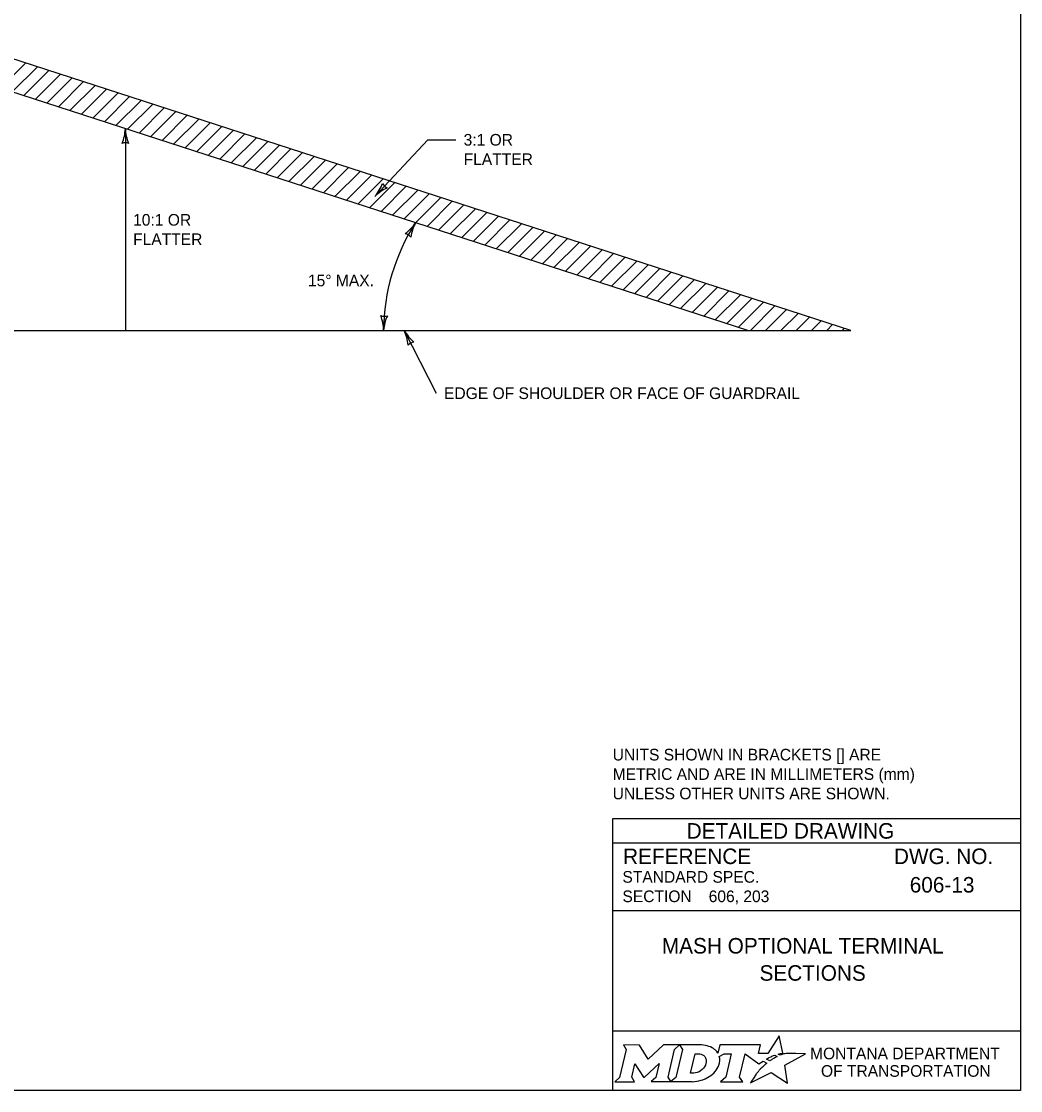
# Model space of a CAD drawing. Extents: x 49991.4 to 50021, y 49987.6 to 50011.4.
# Drawn here: x 50011.61 to 50016.75, y 49987.8 to 49993.3 of the extents above; entities that cross this region are included whole.
import ezdxf

# ---------------------------------------------------------------- set-up
doc = ezdxf.new("R2010")
doc.units = 0
for name, color, linetype in [('Default', 7, 'Continuous'), ('Level 1', 7, 'Continuous'), ('Level 2', 7, 'Continuous'), ('Level 3', 7, 'Continuous'), ('Level 5', 7, 'Continuous')]:
    doc.layers.add(name, color=color, linetype=linetype)

msp = doc.modelspace()

# ---------------------------------------------------------------- linework, layer by layer
at = {"layer": 'Default'}
for points in [[(50015.5126, 49987.9811), (50015.5023, 49987.9867), (50015.5139, 49987.9895), (50015.5255, 49987.9915), (50015.5081, 49988.0816), (50015.4486, 49987.9903), (50015.4013, 49987.9896), (50015.4116, 49988.0337), (50015.2024, 49988.0338), (50015.1923, 49987.9913), (50015.1865, 49987.9996)], [(50014.7056, 49988.0338), (50014.7197, 49988.0104), (50014.6862, 49987.8671), (50014.6605, 49987.8446), (50014.7621, 49987.8446), (50014.7486, 49987.8674), (50014.7648, 49987.9375), (50014.8085, 49987.8685), (50014.8138, 49987.8685), (50014.8889, 49987.938), (50014.8725, 49987.8669), (50014.8478, 49987.8449), (50014.9494, 49987.8449), (50014.9356, 49987.8682), (50014.9688, 49988.0106)], [(50014.9688, 49988.0106), (50014.9941, 49988.0338), (50014.9117, 49988.0338), (50014.8321, 49987.9608), (50014.7876, 49988.0335), (50014.7056, 49988.0338)], [(50015.1077, 49988.0338), (50014.9941, 49988.0338), (50015.0088, 49988.0109), (50014.9749, 49987.8671), (50014.9494, 49987.8449), (50015.06, 49987.8449)], [(50015.1317, 49987.9471), (50015.1305, 49987.939), (50015.1273, 49987.9297), (50015.1231, 49987.9215), (50015.1175, 49987.914), (50015.111, 49987.9071), (50015.1031, 49987.9008), (50015.0948, 49987.8961), (50015.0857, 49987.8922), (50015.0766, 49987.8899), (50015.0674, 49987.889), (50015.0515, 49987.889), (50015.0751, 49987.989), (50015.0911, 49987.989), (50015.0987, 49987.9884), (50015.1063, 49987.9865), (50015.1129, 49987.9835), (50015.119, 49987.9793), (50015.1238, 49987.9743), (50015.1275, 49987.9683), (50015.1302, 49987.9621), (50015.1318, 49987.9547), (50015.1318, 49987.9517), (50015.1317, 49987.9471)], [(50015.1991, 49987.9747), (50015.2237, 49987.9878), (50015.2606, 49987.9878), (50015.232, 49987.8673), (50015.2045, 49987.8446), (50015.3207, 49987.8446), (50015.3037, 49987.8675), (50015.3319, 49987.9877), (50015.4032, 49987.936), (50015.4243, 49987.9511), (50015.444, 49987.9402)], [(50015.3882, 49987.8843), (50015.3729, 49987.8599), (50015.3682, 49987.8524), (50015.3624, 49987.8438), (50015.3601, 49987.8395), (50015.4654, 49987.8926), (50015.5493, 49987.8375), (50015.5362, 49987.9302), (50015.6431, 49987.9886), (50015.5938, 49987.9894), (50015.5637, 49987.9898), (50015.5429, 49987.9901), (50015.5361, 49987.9886), (50015.5312, 49987.9874), (50015.5228, 49987.9851), (50015.5126, 49987.9811)], [(50015.4622, 49987.9535), (50015.4598, 49987.9518), (50015.4415, 49987.9614), (50015.4518, 49987.9671), (50015.4559, 49987.9693), (50015.4645, 49987.9733), (50015.4702, 49987.9759), (50015.4781, 49987.9789), (50015.4854, 49987.9816), (50015.4972, 49987.9742), (50015.4932, 49987.9721), (50015.4886, 49987.9696), (50015.4844, 49987.9674), (50015.4794, 49987.9645), (50015.4775, 49987.9634), (50015.4748, 49987.9618), (50015.4723, 49987.9604), (50015.47, 49987.9588), (50015.4674, 49987.957), (50015.4647, 49987.9552), (50015.4622, 49987.9535)], [(50015.4021, 49987.9004), (50015.4021, 49987.9004)], [(50015.1057, 49987.8522), (50015.1141, 49987.8548), (50015.1271, 49987.8602), (50015.1475, 49987.8712)]]:
    msp.add_lwpolyline(points, dxfattribs=at)
for centre, radius, start, end in [((50015.1308, 49987.9554), 0.0709, 339.5329, 15.8582), ((50015.0868, 49987.9727), 0.1183, 300.9103, 339.1383)]:
    msp.add_arc(centre, radius, start, end, dxfattribs=at)
for centre, major_axis, ratio, start_param, end_param in [((50015.1056, 49987.9864), (0.0834, -0.0037), 0.568097, 0.61298, 1.570796), ((50015.1612, 49987.9937), (0.0361, -0.0295), 0.469099, 1.225588, 1.570796), ((50015.3952, 49987.8923), (-0.00694, -0.00806), 0.008222, 0, 3.137361), ((50015.4119, 49987.9106), (-0.0098, -0.0102), 0.016458, 3.141593, 6.279097), ((50015.4329, 49987.9305), (-0.0112, -0.0097), 0.021651, 3.157348, 6.283185), ((50015.0603, 49987.9932), (0, 0.1484), 0.987302, 3.139398, 3.456847)]:
    msp.add_ellipse(centre, major_axis=major_axis, ratio=ratio, start_param=start_param, end_param=end_param, dxfattribs=at)
at = {"layer": 'Level 1'}
for p, q in [((50015.8765, 49991.7129), (50011.0311, 49993.2847)), ((50015.3468, 49991.713), (50011.0311, 49993.1129)), ((50011.6297, 49993.0905), (50011.5, 49992.9608)), ((50011.6891, 49993.0713), (50011.5594, 49992.9416)), ((50011.7484, 49993.052), (50011.6187, 49992.9223)), ((50011.8077, 49993.0328), (50011.678, 49992.9031)), ((50011.8671, 49993.0135), (50011.7373, 49992.8838)), ((50011.9264, 49992.9943), (50011.7967, 49992.8646)), ((50011.9857, 49992.9751), (50011.856, 49992.8453)), ((50012.045, 49992.9558), (50011.9153, 49992.8261)), ((50012.1044, 49992.9365), (50011.9747, 49992.8069)), ((50012.1637, 49992.9173), (50012.034, 49992.7876)), ((50012.223, 49992.8981), (50012.0933, 49992.7684)), ((50012.2823, 49992.8788), (50012.1526, 49992.7491)), ((50012.3416, 49992.8596), (50012.212, 49992.7299)), ((50012.4009, 49992.8403), (50012.2713, 49992.7106)), ((50012.4603, 49992.8211), (50012.3306, 49992.6914)), ((50012.5197, 49992.8018), (50012.3899, 49992.6722)), ((50012.5789, 49992.7826), (50012.4493, 49992.6529)), ((50012.6382, 49992.7634), (50012.5085, 49992.6337)), ((50012.6976, 49992.7441), (50012.5679, 49992.6144)), ((50012.7569, 49992.7249), (50012.6273, 49992.5952)), ((50012.8162, 49992.7056), (50012.6865, 49992.5759)), ((50012.8756, 49992.6864), (50012.7458, 49992.5567)), ((50012.9348, 49992.6672), (50012.8052, 49992.5374)), ((50012.9942, 49992.6479), (50012.8645, 49992.5182)), ((50013.0535, 49992.6287), (50012.9238, 49992.499)), ((50013.1129, 49992.6094), (50012.9832, 49992.4797)), ((50013.1722, 49992.5902), (50013.0425, 49992.4605)), ((50013.2315, 49992.5709), (50013.1018, 49992.4412)), ((50013.2908, 49992.5517), (50013.1611, 49992.422)), ((50013.3501, 49992.5325), (50013.2205, 49992.4027)), ((50013.4095, 49992.5132), (50013.2798, 49992.3835)), ((50013.4688, 49992.4939), (50013.3391, 49992.3643)), ((50013.5281, 49992.4747), (50013.3985, 49992.345)), ((50013.5875, 49992.4555), (50013.4577, 49992.3258)), ((50013.6467, 49992.4362), (50013.517, 49992.3065)), ((50013.706, 49992.417), (50013.5764, 49992.2873)), ((50013.7654, 49992.3977), (50013.6357, 49992.268)), ((50013.8247, 49992.3785), (50013.695, 49992.2488)), ((50013.8841, 49992.3592), (50013.7543, 49992.2296)), ((50013.9434, 49992.34), (50013.8137, 49992.2103)), ((50014.0027, 49992.3208), (50013.873, 49992.1911)), ((50014.062, 49992.3015), (50013.9323, 49992.1718)), ((50014.1213, 49992.2823), (50013.9916, 49992.1526)), ((50014.1807, 49992.263), (50014.051, 49992.1333)), ((50014.24, 49992.2438), (50014.1103, 49992.1141)), ((50014.2993, 49992.2245), (50014.1696, 49992.0948)), ((50014.3586, 49992.2053), (50014.2289, 49992.0756)), ((50014.418, 49992.186), (50014.2883, 49992.0563)), ((50014.4773, 49992.1668), (50014.3476, 49992.0371)), ((50014.5366, 49992.1476), (50014.4069, 49992.0179)), ((50014.5959, 49992.1283), (50014.4662, 49991.9986)), ((50014.6552, 49992.1091), (50014.5255, 49991.9794)), ((50014.7146, 49992.0898), (50014.5849, 49991.9601)), ((50014.7739, 49992.0706), (50014.6442, 49991.9409)), ((50014.8332, 49992.0514), (50014.7035, 49991.9217)), ((50014.8925, 49992.0321), (50014.7628, 49991.9024)), ((50014.9519, 49992.0129), (50014.8222, 49991.8832)), ((50015.0112, 49991.9936), (50014.8815, 49991.8639)), ((50015.0705, 49991.9744), (50014.9408, 49991.8447)), ((50015.1298, 49991.9551), (50015.0001, 49991.8254)), ((50015.1892, 49991.9359), (50015.0595, 49991.8062)), ((50015.2485, 49991.9167), (50015.1188, 49991.787)), ((50015.3078, 49991.8974), (50015.1781, 49991.7677)), ((50015.3671, 49991.8782), (50015.2374, 49991.7485)), ((50015.4265, 49991.859), (50015.2967, 49991.7292)), ((50015.4265, 49991.8589), (50015.2968, 49991.7292)), ((50015.4858, 49991.8398), (50015.359, 49991.713)), ((50015.5451, 49991.8206), (50015.4375, 49991.713)), ((50015.6044, 49991.8013), (50015.5161, 49991.713)), ((50015.6638, 49991.782), (50015.5947, 49991.713)), ((50015.6636, 49991.7815), (50015.5951, 49991.713)), ((50015.7229, 49991.7622), (50015.6736, 49991.713)), ((50000.2381, 49991.7144), (50015.8765, 49991.7129)), ((50015.7822, 49991.743), (50015.7521, 49991.713)), ((50015.8415, 49991.7238), (50015.8307, 49991.713))]:
    msp.add_line(p, q, dxfattribs=at)
msp.add_lwpolyline([(49999.3835, 49998.9992), (50016.7501, 49998.9992), (50016.7501, 49987.7988), (49999.3835, 49987.7988)], close=True, dxfattribs=at)
at = {"layer": 'Level 3'}
for p, q in [((50012.1416, 49992.7527), (50012.1416, 49991.7133)), ((50013.426, 49992.4031), (50013.6985, 49992.6951)), ((50013.6985, 49992.6951), (50013.8429, 49992.6951)), ((50013.5772, 49991.7132), (50013.7421, 49991.39))]:
    msp.add_line(p, q, dxfattribs=at)
for centre, radius, start, end in [((50011.9089, 49992.7642), 0.233, 337.9228, 357.1727), ((50012.3637, 49992.7618), 0.2223, 182.3605, 202.544), ((50012.1416, 49992.6245), 0.0548, 72.1388, 107.8612), ((50013.2574, 49992.5479), 0.2223, 319.3389, 339.5224), ((50013.5135, 49992.4968), 0.0548, 209.1173, 244.8396), ((50013.5883, 49992.2359), 0.233, 114.9013, 134.1511), ((50014.506, 49991.7074), 1.0352, 147.209, 179.6784), ((50013.4502, 49992.3905), 0.2223, 306.4022, 326.5857), ((50013.841, 49992.1578), 0.233, 151.7735, 171.0234), ((50013.5696, 49992.1582), 0.0548, 41.085, 76.8074), ((50013.4753, 49991.8413), 0.0548, 250.1022, 285.8246), ((50013.2378, 49991.71), 0.233, 0.7907, 20.0406), ((50013.6925, 49991.6962), 0.2223, 155.4194, 175.6029), ((50013.3752, 49991.6204), 0.2223, 4.4872, 24.6707), ((50013.7793, 49991.8292), 0.233, 209.8585, 229.1084), ((50013.6355, 49991.599), 0.0548, 99.17, 134.8924)]:
    msp.add_arc(centre, radius, start, end, dxfattribs=at)
at = {"layer": 'Level 5'}
for p, q in [((50016.7501, 49989.1988), (50014.6501, 49989.1988)), ((50014.6501, 49989.1988), (50014.6501, 49987.7988)), ((50016.7501, 49989.0738), (50014.6501, 49989.0738)), ((50016.3862, 49988.8587), (50016.3862, 49988.8587)), ((50015.1444, 49988.7993), (50015.1444, 49988.7993)), ((50016.7501, 49988.7238), (50014.6501, 49988.7238)), ((50015.7001, 49988.4747), (50015.7001, 49988.4747)), ((50016.7501, 49988.1057), (50014.6501, 49988.1057))]:
    msp.add_line(p, q, dxfattribs=at)

# ---------------------------------------------------------------- texts
at = {"layer": 'Default'}
for s, p in [('MONTANA DEPARTMENT', (50015.6663, 49987.96)), ('OF TRANSPORTATION', (50015.7225, 49987.87))]:
    msp.add_text(s, height=0.06, dxfattribs=at).set_placement(p)
at = {"layer": 'Level 2'}
for s, height, p in [('3:1 OR', 0.06, (50013.8829, 49992.6649)), ('FLATTER', 0.06, (50013.8829, 49992.565)), ('10:1 OR', 0.06, (50012.1816, 49992.2528)), ('FLATTER', 0.06, (50012.1816, 49992.1528)), ('15° MAX.', 0.06, (50013.0817, 49991.9405)), ('EDGE OF SHOULDER OR FACE OF GUARDRAIL', 0.06, (50013.7821, 49991.36)), ('UNITS SHOWN IN BRACKETS [] ARE ', 0.06, (50014.6501, 49989.4988)), ('METRIC AND ARE IN MILLIMETERS (mm)', 0.06, (50014.6501, 49989.3988)), ('UNLESS OTHER UNITS ARE SHOWN.', 0.06, (50014.6501, 49989.2988)), ('606-13', 0.08, (50016.1794, 49988.8187)), ('606, 203', 0.06, (50015.1444, 49988.7693)), ('MASH OPTIONAL TERMINAL', 0.08, (50014.9034, 49988.5046)), ('SECTIONS', 0.08, (50015.4062, 49988.3646))]:
    msp.add_text(s, height=height, dxfattribs=at).set_placement(p)
at = {"layer": 'Level 5'}
for s, height, p in [('DETAILED DRAWING', 0.0799, (50015.0311, 49989.0963)), ('REFERENCE', 0.08, (50014.7037, 49988.9654)), ('DWG. NO.', 0.08, (50016.0979, 49988.9654)), ('STANDARD SPEC.', 0.06, (50014.7004, 49988.8694)), ('SECTION', 0.06, (50014.7004, 49988.7694))]:
    msp.add_text(s, height=height, dxfattribs=at).set_placement(p)

doc.saveas('drawing.dxf')
